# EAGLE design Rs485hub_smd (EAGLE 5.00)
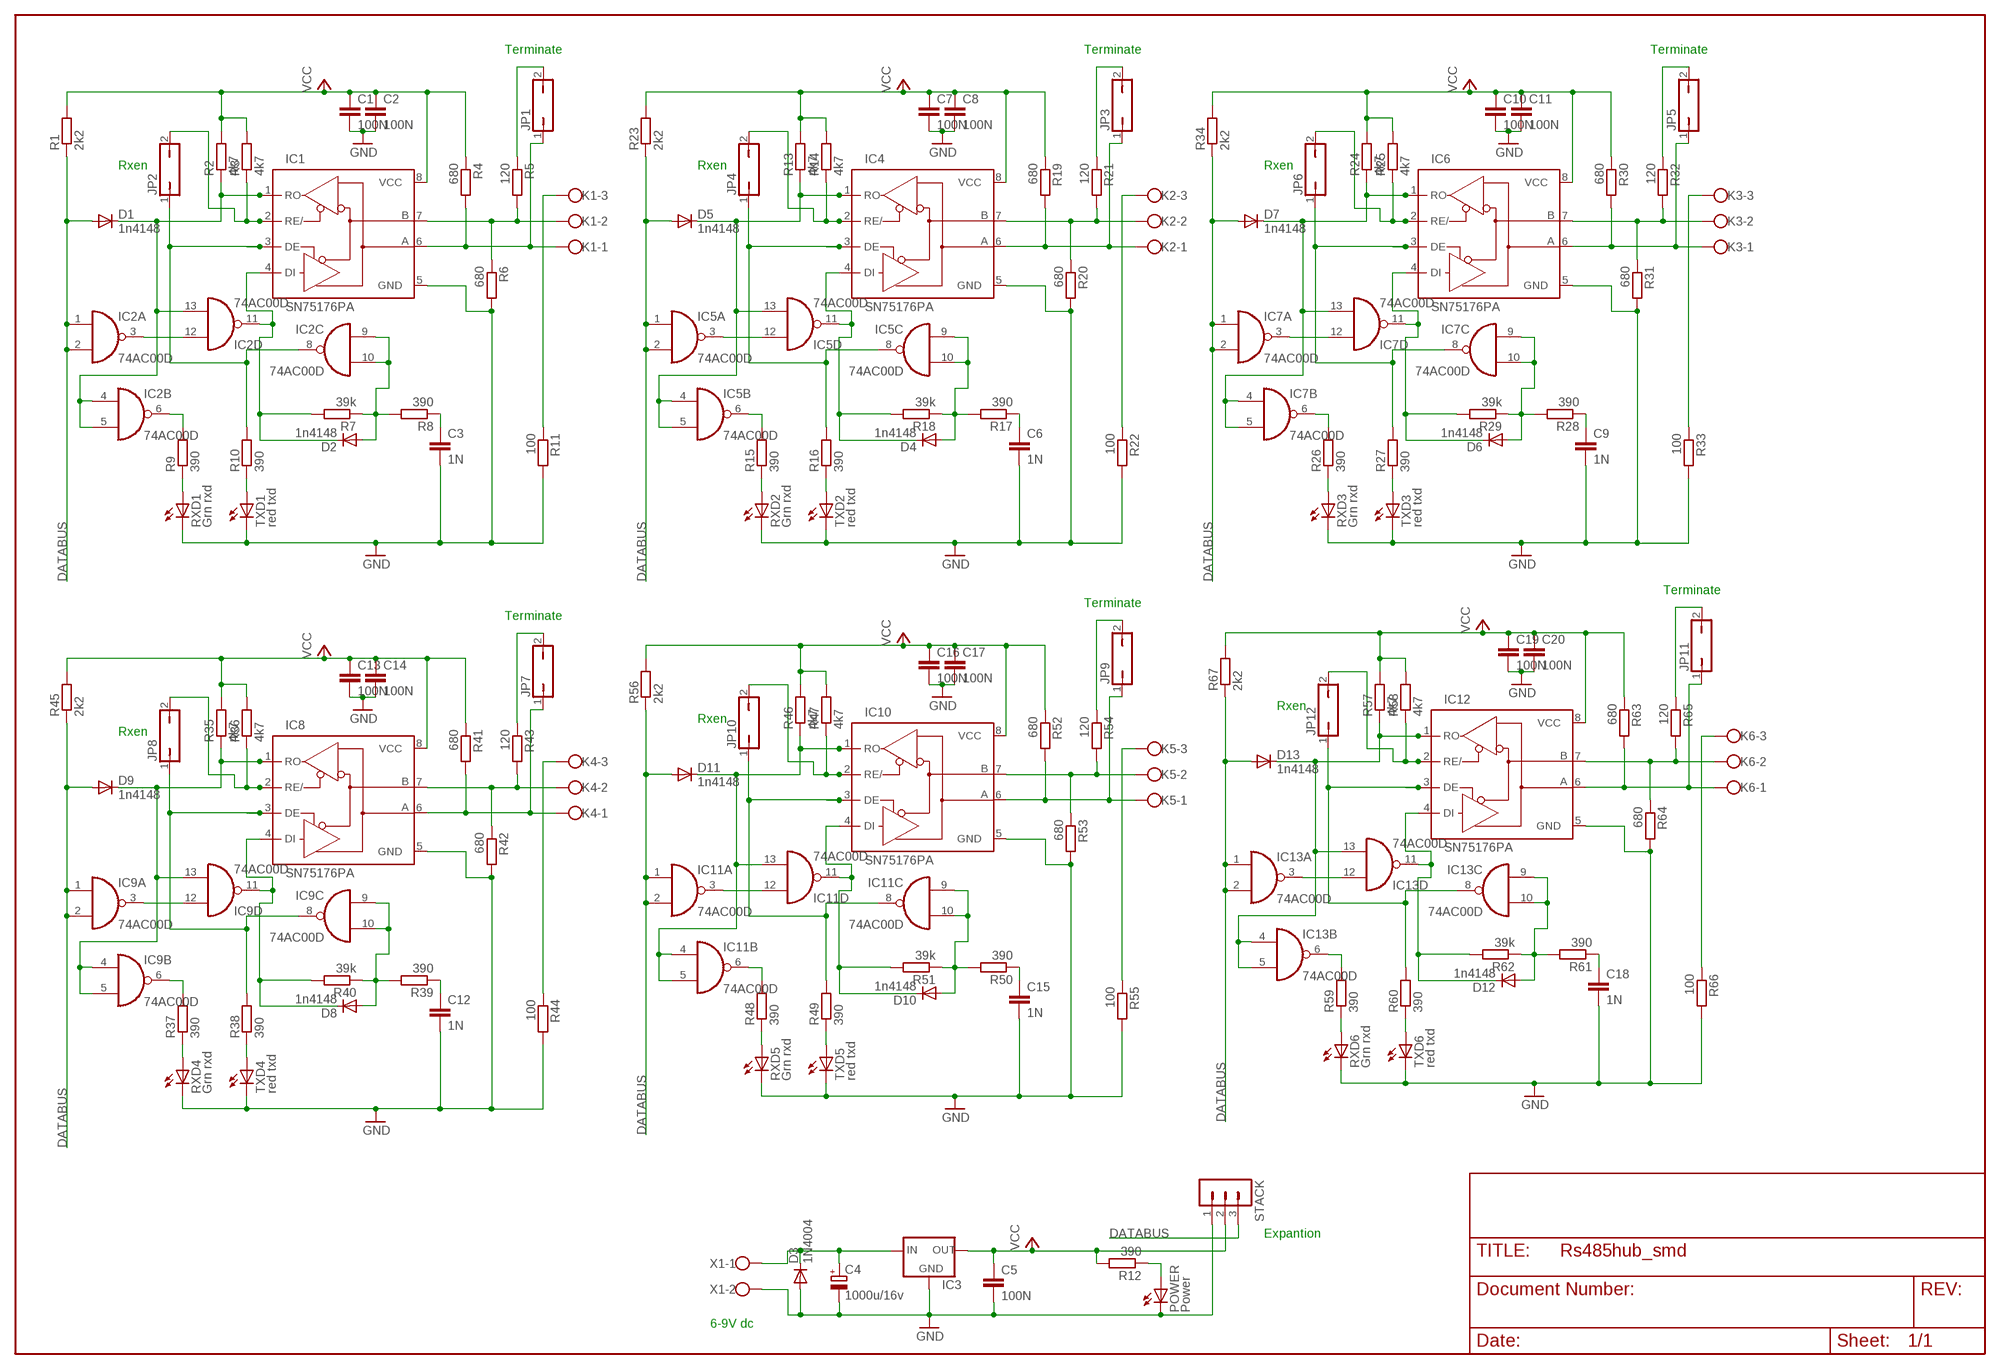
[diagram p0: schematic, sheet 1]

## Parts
C1  100N  C-EUC0805  [C0805]
C2  100N  C-EUC0805  [C0805]
C3  1N  C-EUC0805  [C0805]
C4  1000u/16v  CPOL-EUE5-13  [E5-13]
C5  100N  C-EUC0805  [C0805]
C6  1N  C-EUC0805  [C0805]
C7  100N  C-EUC0805  [C0805]
C8  100N  C-EUC0805  [C0805]
C9  1N  C-EUC0805  [C0805]
C10  100N  C-EUC0805  [C0805]
C11  100N  C-EUC0805  [C0805]
C12  1N  C-EUC0805  [C0805]
C13  100N  C-EUC0805  [C0805]
C14  100N  C-EUC0805  [C0805]
C15  1N  C-EUC0805  [C0805]
C16  100N  C-EUC0805  [C0805]
C17  100N  C-EUC0805  [C0805]
C18  1N  C-EUC0805  [C0805]
C19  100N  C-EUC0805  [C0805]
C20  100N  C-EUC0805  [C0805]
D1  1n4148  DIODE-MINIMELF  [MINIMELF]
D2  1n4148  DIODE-MINIMELF  [MINIMELF]
D3  1N4004  [DO41-10]
D4  1n4148  DIODE-MINIMELF  [MINIMELF]
D5  1n4148  DIODE-MINIMELF  [MINIMELF]
D6  1n4148  DIODE-MINIMELF  [MINIMELF]
D7  1n4148  DIODE-MINIMELF  [MINIMELF]
D8  1n4148  DIODE-MINIMELF  [MINIMELF]
D9  1n4148  DIODE-MINIMELF  [MINIMELF]
D10  1n4148  DIODE-MINIMELF  [MINIMELF]
D11  1n4148  DIODE-MINIMELF  [MINIMELF]
D12  1n4148  DIODE-MINIMELF  [MINIMELF]
D13  1n4148  DIODE-MINIMELF  [MINIMELF]
IC1  SN75176PA  [DIL08]
IC2  74AC00D  [SO14]
IC3  78XXS  [78XXS]
IC4  SN75176PA  [DIL08]
IC5  74AC00D  [SO14]
IC6  SN75176PA  [DIL08]
IC7  74AC00D  [SO14]
IC8  SN75176PA  [DIL08]
IC9  74AC00D  [SO14]
IC10  SN75176PA  [DIL08]
IC11  74AC00D  [SO14]
IC12  SN75176PA  [DIL08]
IC13  74AC00D  [SO14]
JP1  JP1Q  [JP1]
JP2  JP1Q  [JP1]
JP3  JP1Q  [JP1]
JP4  JP1Q  [JP1]
JP5  JP1Q  [JP1]
JP6  JP1Q  [JP1]
JP7  JP1Q  [JP1]
JP8  JP1Q  [JP1]
JP9  JP1Q  [JP1]
JP10  JP1Q  [JP1]
JP11  JP1Q  [JP1]
JP12  JP1Q  [JP1]
K1  STLZ1550-H3K  [STLZ1550-H3]
K2  STLZ1550-H3K  [STLZ1550-H3]
K3  STLZ1550-H3K  [STLZ1550-H3]
K4  STLZ1550-H3K  [STLZ1550-H3]
K5  STLZ1550-H3K  [STLZ1550-H3]
K6  STLZ1550-H3K  [STLZ1550-H3]
POWER  Power  LEDCHIP-LED0805  [CHIP-LED0805]
R1  2k2  R-EU_M0805  [M0805]
R2  4k7  R-EU_M0805  [M0805]
R3  4k7  R-EU_M0805  [M0805]
R4  680  R-EU_M0805  [M0805]
R5  120  R-EU_M0805  [M0805]
R6  680  R-EU_M0805  [M0805]
R7  39k  R-EU_M0805  [M0805]
R8  390  R-EU_M0805  [M0805]
R9  390  R-EU_M0805  [M0805]
R10  390  R-EU_M0805  [M0805]
R11  100  R-EU_M0805  [M0805]
R12  390  R-EU_M0805  [M0805]
R13  4k7  R-EU_M0805  [M0805]
R14  4k7  R-EU_M0805  [M0805]
R15  390  R-EU_M0805  [M0805]
R16  390  R-EU_M0805  [M0805]
R17  390  R-EU_M0805  [M0805]
R18  39k  R-EU_M0805  [M0805]
R19  680  R-EU_M0805  [M0805]
R20  680  R-EU_M0805  [M0805]
R21  120  R-EU_M0805  [M0805]
R22  100  R-EU_M0805  [M0805]
R23  2k2  R-EU_M0805  [M0805]
R24  4k7  R-EU_M0805  [M0805]
R25  4k7  R-EU_M0805  [M0805]
R26  390  R-EU_M0805  [M0805]
R27  390  R-EU_M0805  [M0805]
R28  390  R-EU_M0805  [M0805]
R29  39k  R-EU_M0805  [M0805]
R30  680  R-EU_M0805  [M0805]
R31  680  R-EU_M0805  [M0805]
R32  120  R-EU_M0805  [M0805]
R33  100  R-EU_M0805  [M0805]
R34  2k2  R-EU_M0805  [M0805]
R35  4k7  R-EU_M0805  [M0805]
R36  4k7  R-EU_M0805  [M0805]
R37  390  R-EU_M0805  [M0805]
R38  390  R-EU_M0805  [M0805]
R39  390  R-EU_M0805  [M0805]
R40  39k  R-EU_M0805  [M0805]
R41  680  R-EU_M0805  [M0805]
R42  680  R-EU_M0805  [M0805]
R43  120  R-EU_M0805  [M0805]
R44  100  R-EU_M0805  [M0805]
R45  2k2  R-EU_M0805  [M0805]
R46  4k7  R-EU_M0805  [M0805]
R47  4k7  R-EU_M0805  [M0805]
R48  390  R-EU_M0805  [M0805]
R49  390  R-EU_M0805  [M0805]
R50  390  R-EU_M0805  [M0805]
R51  39k  R-EU_M0805  [M0805]
R52  680  R-EU_M0805  [M0805]
R53  680  R-EU_M0805  [M0805]
R54  120  R-EU_M0805  [M0805]
R55  100  R-EU_M0805  [M0805]
R56  2k2  R-EU_M0805  [M0805]
R57  4k7  R-EU_M0805  [M0805]
R58  4k7  R-EU_M0805  [M0805]
R59  390  R-EU_M0805  [M0805]
R60  390  R-EU_M0805  [M0805]
R61  390  R-EU_M0805  [M0805]
R62  39k  R-EU_M0805  [M0805]
R63  680  R-EU_M0805  [M0805]
R64  680  R-EU_M0805  [M0805]
R65  120  R-EU_M0805  [M0805]
R66  100  R-EU_M0805  [M0805]
R67  2k2  R-EU_M0805  [M0805]
RXD1  Grn rxd  LEDCHIPLED_0805  [CHIPLED_0805]
RXD2  Grn rxd  LEDCHIPLED_0805  [CHIPLED_0805]
RXD3  Grn rxd  LEDCHIPLED_0805  [CHIPLED_0805]
RXD4  Grn rxd  LEDCHIPLED_0805  [CHIPLED_0805]
RXD5  Grn rxd  LEDCHIPLED_0805  [CHIPLED_0805]
RXD6  Grn rxd  LEDCHIPLED_0805  [CHIPLED_0805]
STACK  MA03-1  [MA03-1]
TXD1  red txd  LEDCHIPLED_0805  [CHIPLED_0805]
TXD2  red txd  LEDCHIPLED_0805  [CHIPLED_0805]
TXD3  red txd  LEDCHIPLED_0805  [CHIPLED_0805]
TXD4  red txd  LEDCHIPLED_0805  [CHIPLED_0805]
TXD5  red txd  LEDCHIPLED_0805  [CHIPLED_0805]
TXD6  red txd  LEDCHIPLED_0805  [CHIPLED_0805]
X1  W237-102  [W237-102]

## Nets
DATABUS: D1.A D5.A D7.A D9.A D11.A D13.A IC2.1(A:I0) IC2.2(A:I1) IC5.1(A:I0) IC5.2(A:I1) IC7.1(A:I0) IC7.2(A:I1) IC9.1(A:I0) IC9.2(A:I1) IC11.1(A:I0) IC11.2(A:I1) IC13.1(A:I0) IC13.2(A:I1) R1.1 R23.1 R34.1 R45.1 R56.1 R67.1 STACK.3
GND [Gnd]: C1.2 C2.2 C3.2 C4.- C5.2 C6.2 C7.2 C8.2 C9.2 C10.2 C11.2 C12.2 C13.2 C14.2 C15.2 C16.2 C17.2 C18.2 C19.2 C20.2 D3.A IC1.5(GND) IC3.GND IC4.5(GND) IC6.5(GND) IC8.5(GND) IC10.5(GND) IC12.5(GND) POWER.C R6.2 R11.2 R20.2 R22.2 R31.2 R33.2 R42.2 R44.2 R53.2 R55.2 R64.2 R66.2 RXD1.C RXD2.C RXD3.C RXD4.C RXD5.C RXD6.C STACK.1 TXD1.C TXD2.C TXD3.C TXD4.C TXD5.C TXD6.C X1.2
N$1: R10.1 TXD1.A
N$2: R9.1 RXD1.A
N$3: K1.3 R11.1
N$4: IC1.7(B) K1.2 R5.2 R6.1
N$5: JP1.2 R5.1
N$6: R16.1 TXD2.A
N$7 [Vcc]: C4.+ D3.C IC3.IN X1.1
N$8: D1.C IC1.1(RO) IC2.4(B:I0) IC2.5(B:I1) IC2.13(D:I1) R2.1
N$9: IC2.3(A:O) IC2.12(D:I0)
N$10: IC1.6(A) JP1.1 K1.1 R4.2
N$11: IC2.6(B:O) R9.2
N$12: IC1.3(DE) IC2.8(C:O) JP2.1 R10.2
N$13: IC1.2(RE/) JP2.2 R3.1
N$14: D2.A IC2.9(C:I0) IC2.10(C:I1) R7.1 R8.2
N$15: D2.C IC1.4(DI) IC2.11(D:O) R7.2
N$16: C3.1 R8.1
N$17: R15.1 RXD2.A
N$18: IC4.7(B) K2.2 R20.1 R21.2
N$19: JP3.2 R21.1
N$20: IC4.6(A) JP3.1 K2.1 R19.2
N$21: D5.C IC4.1(RO) IC5.4(B:I0) IC5.5(B:I1) IC5.13(D:I1) R13.1
N$22: IC5.3(A:O) IC5.12(D:I0)
N$23: IC5.6(B:O) R15.2
N$24: IC4.3(DE) IC5.8(C:O) JP4.1 R16.2
N$25: D4.A IC5.9(C:I0) IC5.10(C:I1) R17.2 R18.1
N$26: D4.C IC4.4(DI) IC5.11(D:O) R18.2
N$27: C6.1 R17.1
N$28: IC4.2(RE/) JP4.2 R14.1
N$29: K2.3 R22.1
N$30: R27.1 TXD3.A
N$31: R26.1 RXD3.A
N$32: IC6.7(B) K3.2 R31.1 R32.2
N$33: JP5.2 R32.1
N$34: IC6.6(A) JP5.1 K3.1 R30.2
N$35: D7.C IC6.1(RO) IC7.4(B:I0) IC7.5(B:I1) IC7.13(D:I1) R24.1
N$36: POWER.A R12.1
N$37: IC7.3(A:O) IC7.12(D:I0)
N$38: IC7.6(B:O) R26.2
N$39: IC6.3(DE) IC7.8(C:O) JP6.1 R27.2
N$40: D6.A IC7.9(C:I0) IC7.10(C:I1) R28.2 R29.1
N$41: D6.C IC6.4(DI) IC7.11(D:O) R29.2
N$42: C9.1 R28.1
N$43: IC6.2(RE/) JP6.2 R25.1
N$44: K3.3 R33.1
N$45: R38.1 TXD4.A
N$46: R37.1 RXD4.A
N$47: IC8.7(B) K4.2 R42.1 R43.2
N$48: JP7.2 R43.1
N$49: IC8.6(A) JP7.1 K4.1 R41.2
N$50: D9.C IC8.1(RO) IC9.4(B:I0) IC9.5(B:I1) IC9.13(D:I1) R35.1
N$51: IC9.3(A:O) IC9.12(D:I0)
N$52: IC9.6(B:O) R37.2
N$53: IC8.3(DE) IC9.8(C:O) JP8.1 R38.2
N$54: D8.A IC9.9(C:I0) IC9.10(C:I1) R39.2 R40.1
N$55: D8.C IC8.4(DI) IC9.11(D:O) R40.2
N$56: C12.1 R39.1
N$57: IC8.2(RE/) JP8.2 R36.1
N$58: K4.3 R44.1
N$59: R49.1 TXD5.A
N$60: R48.1 RXD5.A
N$61: IC10.7(B) K5.2 R53.1 R54.2
N$62: JP9.2 R54.1
N$63: IC10.6(A) JP9.1 K5.1 R52.2
N$64: D11.C IC10.1(RO) IC11.4(B:I0) IC11.5(B:I1) IC11.13(D:I1) R46.1
N$65: IC11.3(A:O) IC11.12(D:I0)
N$66: IC11.6(B:O) R48.2
N$67: IC10.3(DE) IC11.8(C:O) JP10.1 R49.2
N$68: D10.A IC11.9(C:I0) IC11.10(C:I1) R50.2 R51.1
N$69: D10.C IC10.4(DI) IC11.11(D:O) R51.2
N$70: C15.1 R50.1
N$71: IC10.2(RE/) JP10.2 R47.1
N$72: K5.3 R55.1
N$73: R60.1 TXD6.A
N$74: R59.1 RXD6.A
N$75: IC12.7(B) K6.2 R64.1 R65.2
N$76: JP11.2 R65.1
N$77: IC12.6(A) JP11.1 K6.1 R63.2
N$78: D13.C IC12.1(RO) IC13.4(B:I0) IC13.5(B:I1) IC13.13(D:I1) R57.1
N$79: IC13.3(A:O) IC13.12(D:I0)
N$80: IC13.6(B:O) R59.2
N$81: IC12.3(DE) IC13.8(C:O) JP12.1 R60.2
N$82: D12.A IC13.9(C:I0) IC13.10(C:I1) R61.2 R62.1
N$83: D12.C IC12.4(DI) IC13.11(D:O) R62.2
N$84: C18.1 R61.1
N$85: IC12.2(RE/) JP12.2 R58.1
N$86: K6.3 R66.1
VCC [Vcc]: C1.1 C2.1 C5.1 C7.1 C8.1 C10.1 C11.1 C13.1 C14.1 C16.1 C17.1 C19.1 C20.1 IC1.8(VCC) IC3.OUT IC4.8(VCC) IC6.8(VCC) IC8.8(VCC) IC10.8(VCC) IC12.8(VCC) R1.2 R2.2 R3.2 R4.1 R12.2 R13.2 R14.2 R19.1 R23.2 R24.2 R25.2 R30.1 R34.2 R35.2 R36.2 R41.1 R45.2 R46.2 R47.2 R52.1 R56.2 R57.2 R58.2 R63.1 R67.2 STACK.2

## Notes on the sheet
- Terminate | Terminate | Terminate
- Rxen | Rxen | Rxen
- Terminate
- Terminate
- Terminate
- Rxen
- Rxen
- Rxen
- Expantion
- 6-9V dc

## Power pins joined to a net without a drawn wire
GND: IC2.7(P:GND) IC5.7(P:GND) IC7.7(P:GND) IC9.7(P:GND) IC11.7(P:GND) IC13.7(P:GND)
VCC: IC2.14(P:VCC) IC5.14(P:VCC) IC7.14(P:VCC) IC9.14(P:VCC) IC11.14(P:VCC) IC13.14(P:VCC)

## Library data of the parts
C1-C3 C5-C20 = rcl:C-EU: CAPACITOR, European symbol
C4 = rcl:CPOL-EU: POLARIZED CAPACITOR, European symbol
D1 D2 D4-D13 = diode:DIODE-: DIODE
D3 = diode:1N4004: DIODE
IC1 IC4 IC6 IC8 IC10 IC12 = Evert:SN75176: +5V, Fail-Safe, 40Mbps, Profibus RS-485/RS-422 Transceivers
IC2 IC5 IC7 IC9 IC11 IC13 = 74xx-eu:74*00: Quad 2-input NAND gate
IC3 = v-reg:78XXS: VOLTAGE REGULATOR
JP1-JP12 = jumper:JP1Q: JUMPER
K1-K6 = Evert:STLZ1550-H3
POWER RXD1-RXD6 TXD1-TXD6 = led:LED: LED
R1-R67 = rcl:R-EU_: RESISTOR, European symbol
STACK = con-lstb:MA03-1: PIN HEADER
X1 = con-wago-500:W237-102: WAGO SCREW CLAMP

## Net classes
0 default: width 0.4 mm, clearance 0.254 mm
1 Vcc: width 0.8 mm, clearance 0.15 mm
2 Gnd: clearance 0.15 mm

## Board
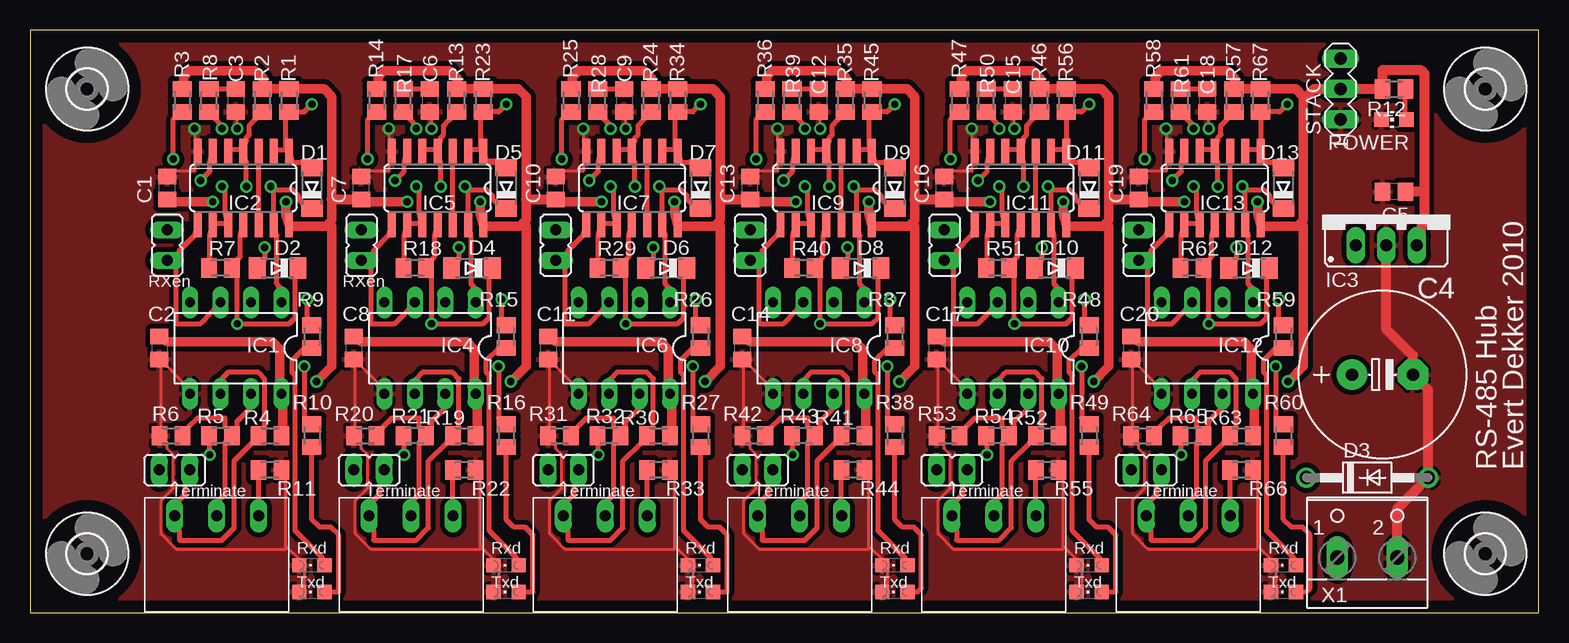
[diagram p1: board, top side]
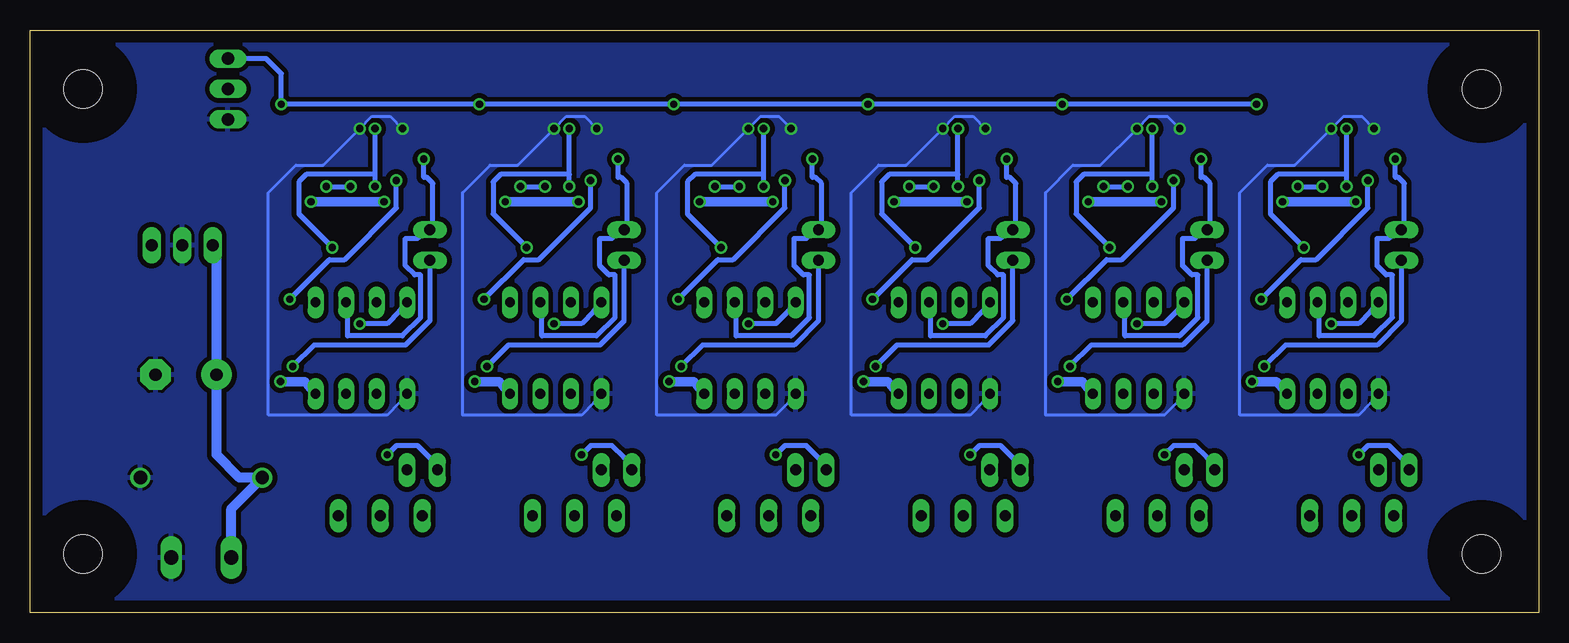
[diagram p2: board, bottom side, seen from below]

Size 125.71 x 48.56 mm. Coordinates in mm from the lower left corner, seen from the top.
Outline: 0,0 125.71,0 125.71,48.56 0,48.56 0,0
Copper layers (1*16): Top 0.035mm / dielectric 1.5mm / Bottom 0.035mm
Design rules "default *": minimum track width 10mil, minimum drill 24mil, track to track 8mil, track to pad 8mil, pad to pad 8mil, via to via 8mil, smd to smd 8mil, copper to edge 40mil, drill to drill 8mil, minimum pad ring 10mil, minimum via ring 8mil, stop-mask expansion 2mil, vias tented up to drill 24mil, thermal gap 10mil

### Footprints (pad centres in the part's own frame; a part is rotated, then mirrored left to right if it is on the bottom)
C0805 = smd 1.3 x 1.5: 1 -0.95,0; 2 0.95,0
E5-13 = drill 1.016 pad 2.54 round: + -2.54,0 | drill 1.016 pad 2.54 octagon: - 2.54,0
MINIMELF = smd 1.4 x 1.8: A 1.7,0; C -1.7,0
DO41-10 = drill 1.118 round: A 5.08,0; C -5.08,0
DIL08 = drill 0.813 long: 1 -3.81,-3.81; 2 -1.27,-3.81; 3 1.27,-3.81; 4 3.81,-3.81; 5 3.81,3.81; 6 1.27,3.81; 7 -1.27,3.81; 8 -3.81,3.81
SO14 = smd 0.66 x 2.032: 1 -3.81,-3.073; 2 -2.54,-3.073; 3 -1.27,-3.073; 4 0,-3.073; 5 1.27,-3.073; 6 2.54,-3.073; 7 3.81,-3.073; 8 3.81,3.073; 9 2.54,3.073; 10 1.27,3.073; 11 0,3.073; 12 -1.27,3.073; 13 -2.54,3.073; 14 -3.81,3.073
78XXS = drill 1.016 long: GND 0,-2.54; IN -2.54,-2.54; OUT 2.54,-2.54
JP1 = drill 0.914 long: 1 0,-1.27; 2 0,1.27
STLZ1550-H3 = drill 0.9 long: 1 0,0; 2 3.5,0; 3 7,0
CHIP-LED0805 = smd 1.2 x 1.2: A 0,-1.05; C 0,1.05
M0805 = smd 1.3 x 1.6: 1 -0.95,0; 2 0.95,0
CHIPLED_0805 = smd 1.2 x 1.2: A 0,-1.05; C 0,1.05
MA03-1 = drill 1.016 long: 1 -2.54,0; 2 0,0; 3 2.54,0
3,2 = hole 3.2: 0,0
W237-102 = drill 1.194 long: 1 -2.5,-1.27; 2 2.5,-1.27

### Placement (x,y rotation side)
C1  11.43,35.4 90 top
C2  10.79,22.06 270 top
C3  17.14,42.7 270 top
C4  112.71,19.84 0 top
C5  113.66,35.08 180 top
C6  33.33,42.7 270 top
C7  27.62,35.4 90 top
C8  26.98,22.06 270 top
C9  49.52,42.7 270 top
C10  43.81,35.4 90 top
C11  43.17,22.06 270 top
C12  65.72,42.7 270 top
C13  60,35.4 90 top
C14  59.37,22.06 270 top
C15  81.91,42.7 270 top
C16  76.19,35.4 90 top
C17  75.56,22.06 270 top
C18  98.1,42.7 270 top
C19  92.39,35.4 90 top
C20  91.75,22.06 270 top
D1  23.49,35.4 90 top
D2  20.63,28.73 180 top
D3  111.44,11.27 0 top
D4  36.83,28.73 180 top
D5  39.68,35.4 90 top
D6  53.02,28.73 180 top
D7  55.88,35.4 90 top
D8  69.21,28.73 180 top
D9  72.07,35.4 90 top
D10  85.4,28.73 180 top
D11  88.26,35.4 90 top
D12  101.59,28.73 180 top
D13  104.45,35.4 90 top
IC1  17.14,22.06 180 top
IC2  17.77,35.4 180 top
IC3  113.03,33.17 0 top
IC4  33.33,22.06 180 top
IC5  33.97,35.4 180 top
IC6  49.52,22.06 180 top
IC7  50.16,35.4 180 top
IC8  65.72,22.06 180 top
IC9  66.35,35.4 180 top
IC10  81.91,22.06 180 top
IC11  82.55,35.4 180 top
IC12  98.1,22.06 180 top
IC13  98.74,35.4 180 top
JP1  12.06,11.9 90 top
JP2  11.43,30.63 0 top
JP3  28.25,11.9 90 top
JP4  27.62,30.63 0 top
JP5  44.45,11.9 90 top
JP6  43.81,30.63 0 top
JP7  60.64,11.9 90 top
JP8  60,30.63 0 top
JP9  76.83,11.9 90 top
JP10  76.19,30.63 0 top
JP11  93.02,11.9 90 top
JP12  92.39,30.63 0 top
K1  12.06,8.09 0 top
K2  28.25,8.09 0 top
K3  44.45,8.09 0 top
K4  60.64,8.09 0 top
K5  76.83,8.09 0 top
K6  93.02,8.09 0 top
POWER  113.66,41.11 90 top
R1  21.59,42.7 90 top
R2  19.36,42.7 90 top
R3  12.7,42.7 90 top
R4  20,14.76 180 top
R5  15.87,14.76 0 top
R6  11.74,14.76 180 top
R7  15.87,28.73 0 top
R8  14.92,42.7 270 top
R9  23.49,23.01 90 top
R10  23.49,14.76 90 top
R11  20,11.9 0 top
R12  113.66,43.65 180 top
R13  35.55,42.7 90 top
R14  28.89,42.7 90 top
R15  39.68,23.01 90 top
R16  39.68,14.76 90 top
R17  31.11,42.7 270 top
R18  32.06,28.73 0 top
R19  36.19,14.76 180 top
R20  27.93,14.76 180 top
R21  32.06,14.76 0 top
R22  36.19,11.9 0 top
R23  37.78,42.7 90 top
R24  51.75,42.7 90 top
R25  45.08,42.7 90 top
R26  55.88,23.01 90 top
R27  55.88,14.76 90 top
R28  47.3,42.7 270 top
R29  48.26,28.73 0 top
R30  52.38,14.76 180 top
R31  44.13,14.76 180 top
R32  48.26,14.76 0 top
R33  52.38,11.9 0 top
R34  53.97,42.7 90 top
R35  67.94,42.7 90 top
R36  61.27,42.7 90 top
R37  72.07,23.01 90 top
R38  72.07,14.76 90 top
R39  63.49,42.7 270 top
R40  64.45,28.73 0 top
R41  68.58,14.76 180 top
R42  60.32,14.76 180 top
R43  64.45,14.76 0 top
R44  68.58,11.9 0 top
R45  70.16,42.7 90 top
R46  84.13,42.7 90 top
R47  77.47,42.7 90 top
R48  88.26,23.01 90 top
R49  88.26,14.76 90 top
R50  79.69,42.7 270 top
R51  80.64,28.73 0 top
R52  84.77,14.76 180 top
R53  76.51,14.76 180 top
R54  80.64,14.76 0 top
R55  84.77,11.9 0 top
R56  86.36,42.7 90 top
R57  100.33,42.7 90 top
R58  93.66,42.7 90 top
R59  104.45,23.01 90 top
R60  104.45,14.76 90 top
R61  95.88,42.7 270 top
R62  96.83,28.73 0 top
R63  100.96,14.76 180 top
R64  92.7,14.76 180 top
R65  96.83,14.76 0 top
R66  100.96,11.9 0 top
R67  102.55,42.7 90 top
RXD1  23.49,3.96 90 top
RXD2  39.68,3.96 90 top
RXD3  55.88,3.96 90 top
RXD4  72.07,3.96 90 top
RXD5  88.26,3.96 90 top
RXD6  104.45,3.96 90 top
STACK  109.22,43.65 90 top
TXD1  23.49,1.74 90 top
TXD2  39.68,1.74 90 top
TXD3  55.88,1.74 90 top
TXD4  72.07,1.74 90 top
TXD5  88.26,1.74 90 top
TXD6  104.45,1.74 90 top
U$1  [3,2]  4.76,4.92 0 top
U$2  [3,2]  4.76,43.65 0 top
U$3  [3,2]  121.28,43.65 0 top
U$4  [3,2]  121.28,4.92 0 top
X1  111.44,5.87 0 top

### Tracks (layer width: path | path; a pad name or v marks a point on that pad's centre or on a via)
DATABUS  (via drill 0.61)
  Top 0.4: D1.A 22.6,37.55 21.84,37.55 IC2.1 21.33,38.57 20.57,38.57 IC2.2 | D5.A 38.79,37.55 38.03,37.55 IC5.1 37.52,38.57 36.76,38.57 IC5.2 | D7.A 54.99,37.55 54.22,37.55 IC7.1 53.72,38.57 52.95,38.57 IC7.2 | D9.A 71.18,37.55 70.42,37.55 IC9.1 69.91,38.57 69.15,38.57 IC9.2 | R56.1 IC11.1 | D11.A 87.37,37.55 86.61,37.55 IC11.1 | IC11.2 85.34,38.57 86.1,38.57 IC11.1 | R67.1 IC13.1 | D13.A 103.56,37.55 102.8,37.55 IC13.1 | IC13.2 101.53,38.57 102.29,38.57 IC13.1
  Top 0.406: R1.1 21.59,42.06 22.22,42.06 | D5.A 39.68,37.3 39.37,37.62 37.78,37.62 | R67.1 104.14,41.75 v104.77,42.38 | v88.26,42.38 87.62,41.74 R56.1 | v72.07,42.38 71.44,41.75 R45.1 69.91,41.49 69.91,38.57 | v55.87,42.38 55.24,41.75 R34.1 53.72,41.49 53.72,38.57 | v39.68,42.38 39.05,41.75 R23.1 37.52,41.49 37.52,38.57 | R1.1 22.86,41.75 v23.49,42.38 | R1.1 21.33,41.49 21.33,38.57
  Bottom 0.406: v23.49,42.38 v39.68,42.38 v55.87,42.38 v72.07,42.38 v88.26,42.38 v104.77,42.38 104.77,44.92 106.04,46.19 STACK.3 109.53,46.19
GND  (via drill 0.61)
  Top 0.254: C1.2 11.93,36.79 13.71,36.79 13.71,37.55 IC2.7 13.71,39.33 v13.71,40.35 | v17.27,40.35 17.27,41.11 C3.2 | IC1.5 12.7,19.01 12.7,19.27 11.43,20.54 C2.2 10.92,20.54 10.92,15.46 R6.2 11.43,14.19 11.43,13.68 11.93,13.17 11.93,10.38 10.92,9.36 10.92,6.57 12.19,5.3 21.33,5.3 21.33,5.55 | TXD1.C 22.86,1.99 22.86,3.52 RXD1.C 22.35,4.53 21.33,5.55 | 21.33,5.55 21.33,11.14 R11.2 | C7.2 28.13,36.79 29.9,36.79 29.9,37.55 IC5.7 29.9,39.33 v29.9,40.35 | v33.46,40.35 33.46,41.11 C6.2 | IC4.5 28.89,19.01 28.89,19.27 27.62,20.54 C8.2 27.11,20.54 27.11,15.46 R20.2 27.62,14.19 27.62,13.68 28.13,13.17 28.13,10.38 27.11,9.36 27.11,6.57 28.38,5.3 37.52,5.3 37.52,5.55 | TXD2.C 39.05,1.99 39.05,3.52 RXD2.C 38.54,4.53 37.52,5.55 | 37.52,5.55 37.52,11.14 R22.2 | C10.2 44.32,36.79 46.1,36.79 46.1,37.55 IC7.7 46.1,39.33 v46.1,40.35 | v49.65,40.35 49.65,41.11 C9.2 | IC6.5 45.08,19.01 45.08,19.27 43.81,20.54 C11.2 43.3,20.54 43.3,15.46 R31.2 43.81,14.19 43.81,13.68 44.32,13.17 44.32,10.38 43.3,9.36 43.3,6.57 44.57,5.3 53.72,5.3 53.72,5.55 | TXD3.C 55.24,1.99 55.24,3.52 RXD3.C 54.73,4.53 53.72,5.55 | 53.72,5.55 53.72,11.14 R33.2 | C13.2 60.51,36.79 62.29,36.79 62.29,37.55 IC9.7 62.29,39.33 v62.29,40.35 | v65.84,40.35 65.84,41.11 C12.2 | IC8.5 61.27,19.01 61.27,19.27 60,20.54 C14.2 59.49,20.54 59.49,15.46 R42.2 60,14.19 60,13.68 60.51,13.17 60.51,10.38 59.49,9.36 59.49,6.57 60.76,5.3 69.91,5.3 69.91,5.55 | TXD4.C 71.43,1.99 71.43,3.52 RXD4.C 70.92,4.53 69.91,5.55 | 69.91,5.55 69.91,11.14 R44.2 | C16.2 76.7,36.79 78.48,36.79 78.48,37.55 IC11.7 78.48,39.33 v78.48,40.35
  Top 0.254: v82.04,40.35 82.04,41.11 C15.2 | IC10.5 77.47,19.01 77.47,19.27 76.19,20.54 C17.2 75.69,20.54 75.69,15.46 R53.2 76.19,14.19 76.19,13.68 76.7,13.17 76.7,10.38 75.69,9.36 75.69,6.57 76.96,5.3 86.1,5.3 86.1,5.55 | TXD5.C 87.62,1.99 87.62,3.52 RXD5.C 87.12,4.53 86.1,5.55 | 86.1,5.55 86.1,11.14 R55.2 | C19.2 92.9,36.79 94.67,36.79 94.67,37.55 IC13.7 94.67,39.33 v94.67,40.35 | v98.23,40.35 98.23,41.11 C18.2 | IC12.5 93.66,19.01 93.66,19.27 92.39,20.54 C20.2 91.88,20.54 91.88,15.46 R64.2 92.39,14.19 92.39,13.68 92.9,13.17 92.9,10.38 91.88,9.36 91.88,6.57 93.15,5.3 102.29,5.3 102.29,5.55 | TXD6.C 103.82,1.99 103.82,3.52 RXD6.C 103.31,4.53 102.29,5.55 | 102.29,5.55 102.29,11.14 R66.2
  Top 0.813: X1.2 113.94,8.69 D3.A 116.52,18.57 C4.- 115.25,21.43 113.03,23.65 IC3.GND 113.03,30.95
  Bottom 0.254: v13.71,40.35 14.73,41.36 16.25,41.36 v17.27,40.35 20.32,37.3 22.6,37.3 24.89,35.01 24.89,16.47 14.98,16.47 13.96,17.49 IC1.5 | v29.9,40.35 30.92,41.36 32.44,41.36 v33.46,40.35 36.51,37.3 38.79,37.3 41.08,35.01 41.08,16.47 31.17,16.47 30.16,17.49 IC4.5 | v46.1,40.35 47.11,41.36 48.64,41.36 v49.65,40.35 52.7,37.3 54.99,37.3 57.27,35.01 57.27,16.47 47.37,16.47 46.35,17.49 IC6.5 | v62.29,40.35 63.3,41.36 64.83,41.36 v65.84,40.35 68.89,37.3 71.18,37.3 73.46,35.01 73.46,16.47 63.56,16.47 62.54,17.49 IC8.5 | v78.48,40.35 79.5,41.36 81.02,41.36 v82.04,40.35 85.08,37.3 87.37,37.3 89.66,35.01 89.66,16.47 79.75,16.47 78.73,17.49 IC10.5 | v94.67,40.35 95.69,41.36 97.21,41.36 v98.23,40.35 101.28,37.3 103.56,37.3 105.85,35.01 105.85,16.47 95.94,16.47 94.93,17.49 IC12.5
  pour Bottom (isolate 0.406): 0.31,48.41 125.41,48.41 125.41,0.15 0.31,0.15
  pour Top (isolate 0.406): 0.31,48.09 124.77,48.09 125.41,47.46 125.41,0.79 0.95,0.79 0.31,1.42
N$1
  Top 0.4: 25.71,1.74 25.71,6.5 25.08,7.14 24.12,7.14 23.49,7.77 R10.1
  Top 0.406: TXD1.A 25.71,1.74
N$2
  Top 0.4: RXD1.A 24.38,4.53 22.09,6.82 22.09,19.77 21.84,20.03 21.84,21.04 22.86,22.06 R9.1
N$3
  Top 0.4: R11.1 19.05,11.14 19.05,9.36 K1.3
N$4
  Top 0.4: R6.1 13.2,15.46 13.96,16.22 16.25,16.22 16.25,15.46 R5.2 | IC1.7 18.28,16.98 17.27,15.96 17.27,15.46 R5.2 | K1.2 15.74,9.36 16.25,9.87 16.25,14.19 R5.2
N$5  (via drill 0.61)
  Top 0.4: v14.98,13.17 14.98,14.19 R5.1
  Bottom 0.4: v14.98,13.17 14.22,13.93 12.44,13.93 11.43,12.92 JP1.2
N$6
  Top 0.4: 41.91,1.74 41.91,6.5 41.27,7.14 40.32,7.14 39.68,7.77 R16.1
  Top 0.406: TXD2.A 41.91,1.74
N$7
  Top 0.813: C4.+ 110.17,20.16
  Bottom 0.813: X1.1 108.94,8.69 D3.C 108.26,11.27 110.17,13.17 C4.+ 110.17,30.32 IC3.IN
N$8  (via drill 0.61)
  Top 0.4: R2.1 18.79,41.11 18.28,40.6 18.28,39.84 18.03,39.59 18.03,39.33 IC2.4 | IC2.5 16.76,38.57 17.52,38.57 IC2.4 | 20.32,35.27 21.84,35.27 22.35,34.76 22.35,34.51 22.6,34.25 D1.C | 20.32,35.27 IC2.13 20.57,31.46 20.57,27.39 20.82,27.14 IC1.1 | v18.03,35.52 18.03,37.55 IC2.4 | 20.32,35.27 v20.06,35.52
  Bottom 0.4: v20.06,35.52 v18.03,35.52
N$9
  Top 0.4: IC2.12 IC2.3
N$10
  Top 0.4: IC1.6 16,19.52 16.5,20.03 19.05,20.03 19.55,19.52 19.55,15.46 R4.2 18.54,14.19 17.01,12.66 17.01,7.07 16,6.06 12.44,6.06 12.44,6.82 K1.1 12.44,9.36 12.95,9.87 12.95,10.63 JP1.1
N$11  (via drill 0.61)
  Top 0.4: v23.11,26.12 23.11,24.6 R9.2 | v14.22,36.03 14.98,36.79 14.98,37.55 IC2.6
  Bottom 0.4: v23.11,26.12 19.81,29.43 18.54,29.43 14.22,33.74 v14.22,36.03
N$12  (via drill 0.61)
  Top 0.4: v22.86,20.54 22.86,16.22 R10.2 | IC2.8 13.71,31.46 12.44,30.19 12.44,29.93 JP2.1 12.19,28.66 12.19,24.09 14.22,24.09 15.23,25.11 IC1.3
  Bottom 0.4: v22.86,20.54 21.08,22.31 13.46,22.31 11.43,24.35 JP2.1
N$13  (via drill 0.61)
  Top 0.4: v11.93,37.81 11.93,41.11 R3.1
  Bottom 0.4: v11.93,37.81 11.93,36.28 11.68,36.28 11.17,35.78 11.17,32.47 JP2.2 12.44,31.2 13.46,31.2 13.46,28.92 12.7,28.16 12.19,28.16 12.19,24.6 13.71,23.08 18.28,23.08 18.28,24.6 IC1.2
N$14  (via drill 0.61)
  Top 0.4: R7.1 14.98,29.43 14.98,31.46 IC2.9 15.49,32.47 16.25,32.47 IC2.10 16.25,33.24 16.25,35.27 v16,35.52 | v16,40.35 16,40.6 15.49,41.11 R8.2 | v19.55,30.44 19.55,29.43 D2.A
  Bottom 0.4: v16,35.52 16,36.54 | 16,36.54 v16,40.35 | v19.55,30.44 22.35,33.24 22.35,35.9 21.71,36.54 16,36.54
N$15  (via drill 0.61)
  Top 0.4: IC2.11 17.52,31.46 17.52,29.68 17.27,29.43 R7.2 17.27,28.16 v17.27,24.09 21.59,24.09 22.09,24.6 22.09,27.9 D2.C
  Bottom 0.4: v17.27,24.09 14.98,24.09 13.96,25.11 IC1.4
N$16
  Top 0.4: C3.1 16.5,43.65 15.49,43.65 R8.1
N$17
  Top 0.4: RXD2.A 40.57,4.53 38.29,6.82 38.29,19.77 38.03,20.03 38.03,21.04 39.05,22.06 R15.1
N$18
  Top 0.4: R20.1 29.4,15.46 30.16,16.22 32.44,16.22 32.44,15.46 R21.2 | IC4.7 34.48,16.98 33.46,15.96 33.46,15.46 R21.2 | K2.2 31.94,9.36 32.44,9.87 32.44,14.19 R21.2
N$19  (via drill 0.61)
  Top 0.4: v31.17,13.17 31.17,14.19 R21.1
  Bottom 0.4: v31.17,13.17 30.41,13.93 28.63,13.93 27.62,12.92 JP3.2
N$20
  Top 0.4: IC4.6 32.19,19.52 32.7,20.03 35.24,20.03 35.75,19.52 35.75,15.46 R19.2 34.73,14.19 33.21,12.66 33.21,7.07 32.19,6.06 28.63,6.06 28.63,6.82 K2.1 28.63,9.36 29.14,9.87 29.14,10.63 JP3.1
N$21  (via drill 0.61)
  Top 0.4: R13.1 34.98,41.11 34.48,40.6 34.48,39.84 34.22,39.59 34.22,39.33 IC5.4 | IC5.5 32.95,38.57 33.71,38.57 IC5.4 | 36.51,35.27 38.03,35.27 38.54,34.76 38.54,34.51 38.79,34.25 D5.C | 36.51,35.27 IC5.13 36.76,31.46 36.76,27.39 37.02,27.14 IC4.1 | v34.22,35.52 34.22,37.55 IC5.4 | 36.51,35.27 v36.25,35.52
  Bottom 0.4: v36.25,35.52 v34.22,35.52
N$22
  Top 0.4: IC5.12 IC5.3
N$23  (via drill 0.61)
  Top 0.4: v39.3,26.12 39.3,24.6 R15.2 | v30.41,36.03 31.17,36.79 31.17,37.55 IC5.6
  Bottom 0.4: v39.3,26.12 36,29.43 34.73,29.43 30.41,33.74 v30.41,36.03
N$24  (via drill 0.61)
  Top 0.4: v39.05,20.54 39.05,16.22 R16.2 | IC5.8 29.9,31.46 28.63,30.19 28.63,29.93 JP4.1 28.38,28.66 28.38,24.09 30.41,24.09 31.43,25.11 IC4.3
  Bottom 0.4: v39.05,20.54 37.27,22.31 29.65,22.31 27.62,24.35 JP4.1
N$25  (via drill 0.61)
  Top 0.4: R18.1 31.17,29.43 31.17,31.46 IC5.9 31.68,32.47 32.44,32.47 IC5.10 32.44,33.24 32.44,35.27 v32.19,35.52 | v32.19,40.35 32.19,40.6 31.68,41.11 R17.2 | v35.75,30.44 35.75,29.43 D4.A
  Bottom 0.4: v32.19,35.52 32.19,36.54 | 32.19,36.54 v32.19,40.35 | v35.75,30.44 38.54,33.24 38.54,35.9 37.9,36.54 32.19,36.54
N$26  (via drill 0.61)
  Top 0.4: IC5.11 33.71,31.46 33.71,29.68 33.46,29.43 R18.2 33.46,28.16 v33.46,24.09 37.78,24.09 38.29,24.6 38.29,27.9 D4.C
  Bottom 0.4: v33.46,24.09 31.17,24.09 30.16,25.11 IC4.4
N$27
  Top 0.4: C6.1 32.7,43.65 31.68,43.65 R17.1
N$28  (via drill 0.61)
  Top 0.4: v28.13,37.81 28.13,41.11 R14.1
  Bottom 0.4: v28.13,37.81 28.13,36.28 27.87,36.28 27.36,35.78 27.36,32.47 JP4.2 28.63,31.2 29.65,31.2 29.65,28.92 28.89,28.16 28.38,28.16 28.38,24.6 29.9,23.08 34.48,23.08 34.48,24.6 IC4.2
N$29
  Top 0.4: R22.1 35.24,11.14 35.24,9.36 K2.3
N$30
  Top 0.4: 58.1,1.74 58.1,6.5 57.46,7.14 56.51,7.14 55.87,7.77 R27.1
  Top 0.406: TXD3.A 58.1,1.74
N$31
  Top 0.4: RXD3.A 56.76,4.53 54.48,6.82 54.48,19.77 54.22,20.03 54.22,21.04 55.24,22.06 R26.1
N$32
  Top 0.4: R31.1 45.59,15.46 46.35,16.22 48.64,16.22 48.64,15.46 R32.2 | IC6.7 50.67,16.98 49.65,15.96 49.65,15.46 R32.2 | K3.2 48.13,9.36 48.64,9.87 48.64,14.19 R32.2
N$33  (via drill 0.61)
  Top 0.4: v47.37,13.17 47.37,14.19 R32.1
  Bottom 0.4: v47.37,13.17 46.6,13.93 44.83,13.93 43.81,12.92 JP5.2
N$34
  Top 0.4: IC6.6 48.38,19.52 48.89,20.03 51.43,20.03 51.94,19.52 51.94,15.46 R30.2 50.92,14.19 49.4,12.66 49.4,7.07 48.38,6.06 44.83,6.06 44.83,6.82 K3.1 44.83,9.36 45.33,9.87 45.33,10.63 JP5.1
N$35  (via drill 0.61)
  Top 0.4: R24.1 51.18,41.11 50.67,40.6 50.67,39.84 50.41,39.59 50.41,39.33 IC7.4 | IC7.5 49.14,38.57 49.91,38.57 IC7.4 | 52.7,35.27 54.22,35.27 54.73,34.76 54.73,34.51 54.99,34.25 D7.C | 52.7,35.27 IC7.13 52.95,31.46 52.95,27.39 53.21,27.14 IC6.1 | v50.41,35.52 50.41,37.55 IC7.4 | 52.7,35.27 v52.45,35.52
  Bottom 0.4: v52.45,35.52 v50.41,35.52
N$36
  Top 0.406: R12.1 114.61,41.21 POWER.A
N$37
  Top 0.4: IC7.12 IC7.3
N$38  (via drill 0.61)
  Top 0.4: v55.49,26.12 55.49,24.6 R26.2 | v46.6,36.03 47.37,36.79 47.37,37.55 IC7.6
  Bottom 0.4: v55.49,26.12 52.19,29.43 50.92,29.43 46.6,33.74 v46.6,36.03
N$39  (via drill 0.61)
  Top 0.4: v55.24,20.54 55.24,16.22 R27.2 | IC7.8 46.1,31.46 44.83,30.19 44.83,29.93 JP6.1 44.57,28.66 44.57,24.09 46.6,24.09 47.62,25.11 IC6.3
  Bottom 0.4: v55.24,20.54 53.46,22.31 45.84,22.31 43.81,24.35 JP6.1
N$40  (via drill 0.61)
  Top 0.4: R29.1 47.37,29.43 47.37,31.46 IC7.9 47.87,32.47 48.64,32.47 IC7.10 48.64,33.24 48.64,35.27 v48.38,35.52 | v48.38,40.35 48.38,40.6 47.87,41.11 R28.2 | v51.94,30.44 51.94,29.43 D6.A
  Bottom 0.4: v48.38,35.52 48.38,36.54 | 48.38,36.54 v48.38,40.35 | v51.94,30.44 54.73,33.24 54.73,35.9 54.1,36.54 48.38,36.54
N$41  (via drill 0.61)
  Top 0.4: IC7.11 49.91,31.46 49.91,29.68 49.65,29.43 R29.2 49.65,28.16 v49.65,24.09 53.97,24.09 54.48,24.6 54.48,27.9 D6.C
  Bottom 0.4: v49.65,24.09 47.37,24.09 46.35,25.11 IC6.4
N$42
  Top 0.4: C9.1 48.89,43.65 47.87,43.65 R28.1
N$43  (via drill 0.61)
  Top 0.4: v44.32,37.81 44.32,41.11 R25.1
  Bottom 0.4: v44.32,37.81 44.32,36.28 44.06,36.28 43.56,35.78 43.56,32.47 JP6.2 44.83,31.2 45.84,31.2 45.84,28.92 45.08,28.16 44.57,28.16 44.57,24.6 46.1,23.08 50.67,23.08 50.67,24.6 IC6.2
N$44
  Top 0.4: R33.1 51.43,11.14 51.43,9.36 K3.3
N$45
  Top 0.4: 74.29,2.06 74.29,6.5 73.66,7.14 72.7,7.14 72.07,7.77 R38.1
  Top 0.406: 74.29,2.06 73.97,1.74 TXD4.A
N$46
  Top 0.4: RXD4.A 72.96,4.53 70.67,6.82 70.67,19.77 70.42,20.03 70.42,21.04 71.43,22.06 R37.1
N$47
  Top 0.4: R42.1 61.78,15.46 62.54,16.22 64.83,16.22 64.83,15.46 R43.2 | IC8.7 66.86,16.98 65.84,15.96 65.84,15.46 R43.2 | K4.2 64.32,9.36 64.83,9.87 64.83,14.19 R43.2
N$48  (via drill 0.61)
  Top 0.4: v63.56,13.17 63.56,14.19 R43.1
  Bottom 0.4: v63.56,13.17 62.8,13.93 61.02,13.93 60,12.92 JP7.2
N$49
  Top 0.4: IC8.6 64.57,19.52 65.08,20.03 67.62,20.03 68.13,19.52 68.13,15.46 R41.2 67.11,14.19 65.59,12.66 65.59,7.07 64.57,6.06 61.02,6.06 61.02,6.82 K4.1 61.02,9.36 61.53,9.87 61.53,10.63 JP7.1
N$50  (via drill 0.61)
  Top 0.4: R35.1 67.37,41.11 66.86,40.6 66.86,39.84 66.61,39.59 66.61,39.33 IC9.4 | IC9.5 65.34,38.57 66.1,38.57 IC9.4 | 68.89,35.27 70.42,35.27 70.92,34.76 70.92,34.51 71.18,34.25 D9.C | 68.89,35.27 IC9.13 69.15,31.46 69.15,27.39 69.4,27.14 IC8.1 | v66.61,35.52 66.61,37.55 IC9.4 | 68.89,35.27 v68.64,35.52
  Bottom 0.4: v68.64,35.52 v66.61,35.52
N$51
  Top 0.4: IC9.12 IC9.3
N$52  (via drill 0.61)
  Top 0.4: v71.69,26.12 71.69,24.6 R37.2 | v62.8,36.03 63.56,36.79 63.56,37.55 IC9.6
  Bottom 0.4: v71.69,26.12 68.38,29.43 67.11,29.43 62.8,33.74 v62.8,36.03
N$53  (via drill 0.61)
  Top 0.4: v71.43,20.54 71.43,16.22 R38.2 | IC9.8 62.29,31.46 61.02,30.19 61.02,29.93 JP8.1 60.76,28.66 60.76,24.09 62.8,24.09 63.81,25.11 IC8.3
  Bottom 0.4: v71.43,20.54 69.65,22.31 62.03,22.31 60,24.35 JP8.1
N$54  (via drill 0.61)
  Top 0.4: R40.1 63.56,29.43 63.56,31.46 IC9.9 64.07,32.47 64.83,32.47 IC9.10 64.83,33.24 64.83,35.27 v64.57,35.52 | v64.57,40.35 64.57,40.6 64.07,41.11 R39.2 | v68.13,30.44 68.13,29.43 D8.A
  Bottom 0.4: v64.57,35.52 64.57,36.54 | 64.57,36.54 v64.57,40.35 | v68.13,30.44 70.92,33.24 70.92,35.9 70.29,36.54 64.57,36.54
N$55  (via drill 0.61)
  Top 0.4: IC9.11 66.1,31.46 66.1,29.68 65.84,29.43 R40.2 65.84,28.16 v65.84,24.09 70.16,24.09 70.67,24.6 70.67,27.9 D8.C
  Bottom 0.4: v65.84,24.09 63.56,24.09 62.54,25.11 IC8.4
N$56
  Top 0.4: C12.1 65.08,43.65 64.07,43.65 R39.1
N$57  (via drill 0.61)
  Top 0.4: v60.51,37.81 60.51,41.11 R36.1
  Bottom 0.4: v60.51,37.81 60.51,36.28 60.26,36.28 59.75,35.78 59.75,32.47 JP8.2 61.02,31.2 62.03,31.2 62.03,28.92 61.27,28.16 60.76,28.16 60.76,24.6 62.29,23.08 66.86,23.08 66.86,24.6 IC8.2
N$58
  Top 0.4: R44.1 67.62,11.14 67.62,9.36 K4.3
N$59
  Top 0.4: 90.48,1.74 90.48,6.5 89.85,7.14 88.89,7.14 88.26,7.77 R49.1
  Top 0.406: TXD5.A 90.48,1.74
N$60
  Top 0.4: RXD5.A 89.15,4.53 86.86,6.82 86.86,19.77 86.61,20.03 86.61,21.04 87.62,22.06 R48.1
N$61
  Top 0.4: R53.1 77.97,15.46 78.73,16.22 81.02,16.22 81.02,15.46 R54.2 | IC10.7 83.05,16.98 82.04,15.96 82.04,15.46 R54.2 | K5.2 80.51,9.36 81.02,9.87 81.02,14.19 R54.2
N$62  (via drill 0.61)
  Top 0.4: v79.75,13.17 79.75,14.19 R54.1
  Bottom 0.4: v79.75,13.17 78.99,13.93 77.21,13.93 76.19,12.92 JP9.2
N$63
  Top 0.4: IC10.6 80.77,19.52 81.28,20.03 83.81,20.03 84.32,19.52 84.32,15.46 R52.2 83.31,14.19 81.78,12.66 81.78,7.07 80.77,6.06 77.21,6.06 77.21,6.82 K5.1 77.21,9.36 77.72,9.87 77.72,10.63 JP9.1
N$64  (via drill 0.61)
  Top 0.4: R46.1 83.56,41.11 83.05,40.6 83.05,39.84 82.8,39.59 82.8,39.33 IC11.4 | IC11.5 81.53,38.57 82.29,38.57 IC11.4 | 85.08,35.27 86.61,35.27 87.12,34.76 87.12,34.51 87.37,34.25 D11.C | 85.08,35.27 IC11.13 85.34,31.46 85.34,27.39 85.59,27.14 IC10.1 | v82.8,35.52 82.8,37.55 IC11.4 | 85.08,35.27 v84.83,35.52
  Bottom 0.4: v84.83,35.52 v82.8,35.52
N$65
  Top 0.4: IC11.12 IC11.3
N$66  (via drill 0.61)
  Top 0.4: v87.88,26.12 87.88,24.6 R48.2 | v78.99,36.03 79.75,36.79 79.75,37.55 IC11.6
  Bottom 0.4: v87.88,26.12 84.58,29.43 83.31,29.43 78.99,33.74 v78.99,36.03
N$67  (via drill 0.61)
  Top 0.4: v87.62,20.54 87.62,16.22 R49.2 | IC11.8 78.48,31.46 77.21,30.19 77.21,29.93 JP10.1 76.96,28.66 76.96,24.09 78.99,24.09 80,25.11 IC10.3
  Bottom 0.4: v87.62,20.54 85.85,22.31 78.23,22.31 76.19,24.35 JP10.1
N$68  (via drill 0.61)
  Top 0.4: R51.1 79.75,29.43 79.75,31.46 IC11.9 80.26,32.47 81.02,32.47 IC11.10 81.02,33.24 81.02,35.27 v80.77,35.52 | v80.77,40.35 80.77,40.6 80.26,41.11 R50.2 | v84.32,30.44 84.32,29.43 D10.A
  Bottom 0.4: v80.77,35.52 80.77,36.54 | 80.77,36.54 v80.77,40.35 | v84.32,30.44 87.12,33.24 87.12,35.9 86.48,36.54 80.77,36.54
N$69  (via drill 0.61)
  Top 0.4: IC11.11 82.29,31.46 82.29,29.68 82.04,29.43 R51.2 82.04,28.16 v82.04,24.09 86.36,24.09 86.86,24.6 86.86,27.9 D10.C
  Bottom 0.4: v82.04,24.09 79.75,24.09 78.73,25.11 IC10.4
N$70
  Top 0.4: C15.1 81.28,43.65 80.26,43.65 R50.1
N$71  (via drill 0.61)
  Top 0.4: v76.7,37.81 76.7,41.11 R47.1
  Bottom 0.4: v76.7,37.81 76.7,36.28 76.45,36.28 75.94,35.78 75.94,32.47 JP10.2 77.21,31.2 78.23,31.2 78.23,28.92 77.47,28.16 76.96,28.16 76.96,24.6 78.48,23.08 83.05,23.08 83.05,24.6 IC10.2
N$72
  Top 0.4: R55.1 83.81,11.14 83.81,9.36 K5.3
N$73
  Top 0.4: 106.67,2.06 106.67,6.5 106.04,7.14 105.09,7.14 104.45,7.77 R60.1
  Top 0.406: 106.67,2.06 106.36,1.74 TXD6.A
N$74
  Top 0.4: RXD6.A 105.34,4.53 103.06,6.82 103.06,19.77 102.8,20.03 102.8,21.04 103.82,22.06 R59.1
N$75
  Top 0.4: R64.1 94.17,15.46 94.93,16.22 97.21,16.22 97.21,15.46 R65.2 | IC12.7 99.25,16.98 98.23,15.96 98.23,15.46 R65.2 | K6.2 96.71,9.36 97.21,9.87 97.21,14.19 R65.2
N$76  (via drill 0.61)
  Top 0.4: v95.94,13.17 95.94,14.19 R65.1
  Bottom 0.4: v95.94,13.17 95.18,13.93 93.4,13.93 92.39,12.92 JP11.2
N$77
  Top 0.4: IC12.6 96.96,19.52 97.47,20.03 100.01,20.03 100.52,19.52 100.52,15.46 R63.2 99.5,14.19 97.98,12.66 97.98,7.07 96.96,6.06 93.4,6.06 93.4,6.82 K6.1 93.4,9.36 93.91,9.87 93.91,10.63 JP11.1
N$78  (via drill 0.61)
  Top 0.4: R57.1 99.75,41.11 99.25,40.6 99.25,39.84 98.99,39.59 98.99,39.33 IC13.4 | IC13.5 97.72,38.57 98.48,38.57 IC13.4 | 101.28,35.27 102.8,35.27 103.31,34.76 103.31,34.51 103.56,34.25 D13.C | 101.28,35.27 IC13.13 101.53,31.46 101.53,27.39 101.79,27.14 IC12.1 | v98.99,35.52 98.99,37.55 IC13.4 | 101.28,35.27 v101.02,35.52
  Bottom 0.4: v101.02,35.52 v98.99,35.52
N$79
  Top 0.4: IC13.12 IC13.3
N$80  (via drill 0.61)
  Top 0.4: v104.07,26.12 104.07,24.6 R59.2 | v95.18,36.03 95.94,36.79 95.94,37.55 IC13.6
  Bottom 0.4: v104.07,26.12 100.77,29.43 99.5,29.43 95.18,33.74 v95.18,36.03
N$81  (via drill 0.61)
  Top 0.4: v103.82,20.54 103.82,16.22 R60.2 | IC13.8 94.67,31.46 93.4,30.19 93.4,29.93 JP12.1 93.15,28.66 93.15,24.09 95.18,24.09 96.2,25.11 IC12.3
  Bottom 0.4: v103.82,20.54 102.04,22.31 94.42,22.31 92.39,24.35 JP12.1
N$82  (via drill 0.61)
  Top 0.4: R62.1 95.94,29.43 95.94,31.46 IC13.9 96.45,32.47 97.21,32.47 IC13.10 97.21,33.24 97.21,35.27 v96.96,35.52 | v96.96,40.35 96.96,40.6 96.45,41.11 R61.2 | v100.52,30.44 100.52,29.43 D12.A
  Bottom 0.4: v96.96,35.52 96.96,36.54 | 96.96,36.54 v96.96,40.35 | v100.52,30.44 103.31,33.24 103.31,35.9 102.67,36.54 96.96,36.54
N$83  (via drill 0.61)
  Top 0.4: IC13.11 98.48,31.46 98.48,29.68 98.23,29.43 R62.2 98.23,28.16 v98.23,24.09 102.55,24.09 103.06,24.6 103.06,27.9 D12.C
  Bottom 0.4: v98.23,24.09 95.94,24.09 94.93,25.11 IC12.4
N$84
  Top 0.4: C18.1 97.47,43.65 96.45,43.65 R61.1
N$85  (via drill 0.61)
  Top 0.4: v92.9,37.81 92.9,41.11 R58.1
  Bottom 0.4: v92.9,37.81 92.9,36.28 92.64,36.28 92.13,35.78 92.13,32.47 JP12.2 93.4,31.2 94.42,31.2 94.42,28.92 93.66,28.16 93.15,28.16 93.15,24.6 94.67,23.08 99.25,23.08 99.25,24.6 IC12.2
N$86
  Top 0.4: R66.1 100.01,11.14 100.01,9.36 K6.3
VCC  (via drill 0.61)
  Top 0.8: C2.1 11.43,22.57 20.19,22.57 20.82,21.93 20.82,19.52 IC1.8 21.08,16.98 21.08,15.46 R4.1 | R3.2 12.82,43.52 12.82,44.67 13.33,45.17 18.79,45.17 19.43,44.54 19.43,44.16 R2.2 19.74,43.65 20.82,43.65 R1.2 22.35,43.65 24.51,43.65 25.14,43.02 25.14,34.44 25.14,32.73 24.89,32.47 | v15.23,34.25 11.93,34.25 C1.1 | v21.33,34.25 21.33,33.24 IC2.14 21.84,32.22 24.63,32.22 24.89,32.47 | v23.87,19.27 25.14,20.54 25.14,32.22 24.89,32.47 | C8.1 27.62,22.57 36.38,22.57 37.02,21.93 37.02,19.52 IC4.8 37.27,16.98 37.27,15.46 R19.1 | R14.2 29.01,43.52 29.01,44.67 29.52,45.17 34.98,45.17 35.62,44.54 35.62,44.16 R13.2 35.94,43.65 37.02,43.65 R23.2 38.54,43.65 40.7,43.65 41.33,43.02 41.33,34.44 41.33,32.73 41.08,32.47 | v31.43,34.25 28.13,34.25 C7.1 | v37.52,34.25 37.52,33.24 IC5.14 38.03,32.22 40.83,32.22 41.08,32.47 | v40.06,19.27 41.33,20.54 41.33,32.22 41.08,32.47 | C11.1 43.81,22.57 52.57,22.57 53.21,21.93 53.21,19.52 IC6.8 53.46,16.98 53.46,15.46 R30.1 | R25.2 45.21,43.52 45.21,44.67 45.72,45.17 51.18,45.17 51.81,44.54 51.81,44.16 R24.2 52.13,43.65 53.21,43.65 R34.2 54.73,43.65 56.89,43.65 57.53,43.02 57.53,34.44 57.53,32.73 57.27,32.47 | v47.62,34.25 44.32,34.25 C10.1 | v53.72,34.25 53.72,33.24 IC7.14 54.22,32.22 57.02,32.22 57.27,32.47 | v56.26,19.27 57.53,20.54 57.53,32.22 57.27,32.47 | C14.1 60,22.57 68.77,22.57 69.4,21.93 69.4,19.52 IC8.8 69.65,16.98 69.65,15.46 R41.1 | R36.2 61.4,43.52 61.4,44.67 61.91,45.17 67.37,45.17 68,44.54 68,44.16 R35.2 68.32,43.65 69.4,43.65 R45.2 70.92,43.65 73.08,43.65 73.72,43.02 73.72,34.44 73.72,32.73 73.46,32.47
  Top 0.8: v63.81,34.25 60.51,34.25 C13.1 | v69.91,34.25 69.91,33.24 IC9.14 70.42,32.22 73.21,32.22 73.46,32.47 | v72.45,19.27 73.72,20.54 73.72,32.22 73.46,32.47 | C17.1 76.19,22.57 84.96,22.57 85.59,21.93 85.59,19.52 IC10.8 85.85,16.98 85.85,15.46 R52.1 | R47.2 77.59,43.52 77.59,44.67 78.1,45.17 83.56,45.17 84.2,44.54 84.2,44.16 R46.2 84.51,43.65 85.59,43.65 R56.2 87.12,43.65 89.28,43.65 89.91,43.02 89.91,34.44 89.91,32.73 89.66,32.47 | v80,34.25 76.7,34.25 C16.1 | v86.1,34.25 86.1,33.24 IC11.14 86.61,32.22 89.4,32.22 89.66,32.47 | v88.64,19.27 89.91,20.54 89.91,32.22 89.66,32.47 | C20.1 92.39,22.57 101.15,22.57 101.79,21.93 101.79,19.52 IC12.8 102.04,16.98 102.04,15.46 R63.1 | R58.2 93.78,43.52 93.78,44.67 94.29,45.17 99.75,45.17 100.39,44.54 100.39,44.16 R57.2 100.71,43.65 101.79,43.65 R67.2 103.31,43.65 105.47,43.65 106.1,43.02 106.1,32.73 105.85,32.47 | v96.2,34.25 92.9,34.25 C19.1 | v102.29,34.25 102.29,33.24 IC13.14 102.8,32.22 105.6,32.22 105.85,32.47 | v104.83,19.27 106.1,20.54 106.1,32.22 105.85,32.47
  Top 0.813: 106.1,43.02 106.36,43.02 106.99,43.65 STACK.2 R12.2 112.71,45.23 112.71,45.24 115.88,45.24 116.2,44.92 116.2,35.08 | 116.2,35.08 116.2,33.17 IC3.OUT | 116.2,35.08 C5.1 | 89.91,34.44 90.17,34.44 90.17,34.45 C19.1 | 73.72,34.44 73.97,34.44 73.97,34.45 C16.1 | 57.53,34.44 57.78,34.44 57.78,34.45 C13.1 | 41.33,34.44 41.59,34.44 41.59,34.45 C10.1 | 25.14,34.44 25.39,34.44 25.4,34.45 C7.1
  Bottom 0.8: v21.33,34.25 v15.23,34.25 | v23.87,19.27 21.84,19.27 21.59,19.01 IC1.8 | v31.43,34.25 v37.52,34.25 | v40.06,19.27 38.03,19.27 37.78,19.01 IC4.8 | v47.62,34.25 v53.72,34.25 | v56.26,19.27 54.22,19.27 53.97,19.01 IC6.8 | v63.81,34.25 v69.91,34.25 | v72.45,19.27 70.42,19.27 70.16,19.01 IC8.8 | v80,34.25 v86.1,34.25 | v88.64,19.27 86.61,19.27 86.36,19.01 IC10.8 | v96.2,34.25 v102.29,34.25 | v104.83,19.27 102.8,19.27 102.55,19.01 IC12.8

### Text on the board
tNames: RXen | RXen | RS-485 Hub | Evert Dekker 2010 | Terminate | Terminate | Terminate | Terminate | Terminate | Terminate | Rxd | Rxd | Rxd | Rxd | Rxd | Rxd | Txd | Txd | Txd | Txd | Txd | Txd
tStop: Evert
